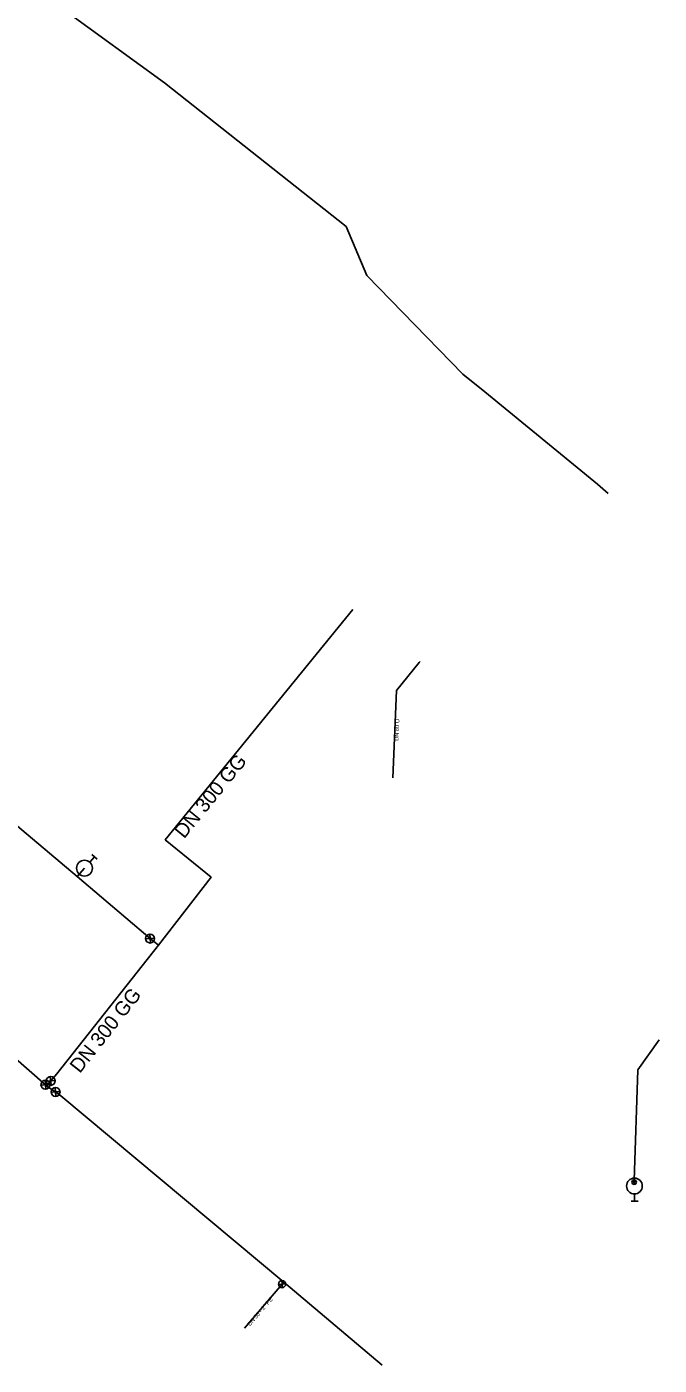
# Model space of a CAD drawing. Extents: x -443519 to -443021, y -1121477 to -1120870.
# Drawn here: x -443092 to -443021.5, y -1121476.7 to -1121327.4 of the extents above; entities that cross this region are included whole.
import ezdxf

# ---------------------------------------------------------------- set-up
doc = ezdxf.new("R2010")
doc.units = 0
for name, color, linetype in [('_hydrantova_odbocka_', 7, 'Continuous'), ('_pripojka_priblizne_', 7, 'Continuous'), ('_voda_smvak_prevzato_z_dokumentace_', 7, 'Continuous'), ('Default', 7, 'Continuous'), ('MoLevel 27', 7, 'Continuous'), ('MoLevel 28', 7, 'Continuous'), ('MoLevel 32', 7, 'Continuous'), ('MoLevel 46', 7, 'Continuous'), ('MoLevel 53', 7, 'Continuous')]:
    doc.layers.add(name, color=color, linetype=linetype)

# ---------------------------------------------------------------- blocks, each defined once
blk = doc.blocks.new('_uzaver_')
at = {"layer": 'Default'}
for p, q in [((-0.000035, -0.000035), (0.000035, 0.000035)), ((0.000035, -0.000035), (-0.000035, 0.000035))]:
    blk.add_line(p, q, dxfattribs=at)
for radius in [0.00005, 0.0000025]:
    blk.add_circle((0, 0), radius, dxfattribs=at)
blk = doc.blocks.new('_uzaver_pripojka_')
at = {"layer": 'Default'}
for p, q in [((-0.000035, -0.000035), (0.000035, 0.000035)), ((0.000035, -0.000035), (-0.000035, 0.000035))]:
    blk.add_line(p, q, dxfattribs=at)
for radius in [0.00005, 0.0000025]:
    blk.add_circle((0, 0), radius, dxfattribs=at)
blk = doc.blocks.new('_hydrant_voda_')
at = {"layer": 'Default'}
for p, q in [((-0.0000225, 0.000095), (0.0000225, 0.000095)), ((0, 0.000095), (0, 0.00005))]:
    blk.add_line(p, q, dxfattribs=at)
blk.add_circle((0, 0), 0.00005, dxfattribs=at)

msp = doc.modelspace()

# ---------------------------------------------------------------- linework, layer by layer
at = {"layer": '_hydrantova_odbocka_'}
msp.add_line((-443086.38, -1121422.16), (-443085.55, -1121421.23), dxfattribs=at)
at = {"layer": '_pripojka_priblizne_'}
for points in [[(-443048.11, -1121398.19), (-443048.22, -1121398.32), (-443050.75, -1121401.43), (-443051.18, -1121411.16)], [(-443063.31, -1121467.38), (-443063.51, -1121467.61), (-443067.72, -1121472.51)]]:
    msp.add_lwpolyline(points, dxfattribs=at)
at = {"layer": '_voda_smvak_prevzato_z_dokumentace_'}
for p, q in [((-443078.23, -1121429.08), (-443086.38, -1121422.16)), ((-443077.29, -1121429.81), (-443078.23, -1121429.08)), ((-443077.29, -1121429.81), (-443088.63, -1121444.16)), ((-443089.9, -1121445.38), (-443093.55, -1121442.21)), ((-443089.74, -1121445.53), (-443089.9, -1121445.38)), ((-443089.31, -1121444.95), (-443089.74, -1121445.53)), ((-443088.63, -1121444.16), (-443089.31, -1121444.95)), ((-443089.74, -1121445.53), (-443088.78, -1121446.18))]:
    msp.add_line(p, q, dxfattribs=at)
for points in [[(-443027.13, -1121379.47), (-443028.32, -1121378.44), (-443040.91, -1121368.14), (-443043.34, -1121366.14), (-443054.07, -1121355.17), (-443056.37, -1121349.71), (-443076.63, -1121333.69), (-443087.9, -1121325.51), (-443098.89, -1121316.36), (-443115.85, -1121301.92), (-443117.14, -1121299.83), (-443127.63, -1121293.04), (-443137.86, -1121284.27), (-443144.91, -1121279.74), (-443163.69, -1121263.91), (-443183.42, -1121246.92), (-443200.48, -1121231.27), (-443212.46, -1121219.38), (-443226.3, -1121205.42), (-443234.86, -1121195.13), (-443243.22, -1121185.2), (-443249.33, -1121177.99)], [(-443086.38, -1121422.16), (-443138.38, -1121378.35), (-443142.4, -1121374.87)], [(-443077.29, -1121429.81), (-443071.43, -1121422.25), (-443076.55, -1121418.07), (-443055.62, -1121392.41)], [(-443024.25, -1121456.24), (-443024.24, -1121456.05), (-443023.85, -1121443.71), (-443021.45, -1121440.38)], [(-443088.78, -1121446.18), (-443088.2, -1121446.63), (-443063.31, -1121467.38), (-443052.36, -1121476.66)]]:
    msp.add_lwpolyline(points, dxfattribs=at)

# ---------------------------------------------------------------- block references
at = {"layer": 'MoLevel 27'}
for p, xscale, yscale, rotation in [((-443078.23, -1121429.08), 10000, 10000, -40.088769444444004), ((-443089.9, -1121445.38), 10000, 10000, -38.909822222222), ((-443089.31, -1121444.95), 10000, 10000, 50.798075), ((-443088.78, -1121446.18), 10000, 10000, -40.238394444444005), ((-443024.25, -1121456.24), 5000, 5000, 85.2620944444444)]:
    msp.add_blockref('_uzaver_', p, dxfattribs=dict(at, xscale=xscale, yscale=yscale, rotation=rotation))
at = {"layer": 'MoLevel 28', "yscale": 17636.68430335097}
for p, xscale, rotation in [((-443085.55, -1121421.23), 17636.684303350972, -42.013299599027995), ((-443024.22, -1121456.68), 17636.684303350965, -179.34990833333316)]:
    msp.add_blockref('_hydrant_voda_', p, dxfattribs=dict(at, xscale=xscale, rotation=rotation))
at = {"layer": 'MoLevel 53', "xscale": 7999.999999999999, "yscale": 8000.000000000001, "rotation": -129.05495716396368}
msp.add_blockref('_uzaver_pripojka_', (-443063.51, -1121467.61), dxfattribs=at)

# ---------------------------------------------------------------- texts
at = {"layer": 'MoLevel 32'}
for s, rotation, p in [('DN 80 O', 87.5136, (-443050.54, -1121407.04)), ("DN 50 - 2'' PE", 49.3128, (-443067.09, -1121472.32))]:
    msp.add_text(s, height=0.455, rotation=rotation, dxfattribs=at).set_placement(p)
at = {"layer": 'MoLevel 46'}
for rotation, p in [(50.8, (-443074.44, -1121418.03)), (51.6869, (-443086.07, -1121444.19))]:
    msp.add_text('DN 300 GG', height=1.605, rotation=rotation, dxfattribs=at).set_placement(p)

doc.saveas('drawing.dxf')
